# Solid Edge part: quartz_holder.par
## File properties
Title: Quartz Window Clamp
Author: Lee Sichello
Template: Iso Part.par
Last saved by: Lee
Revision: 70
Application: Solid Edge
Material: Aluminum
Face Style: Steel
Fill Style: ANSI32(Steel)
Virtual Style: Machined steel
Coef. of Thermal Exp: 1.3e-05
Thermal Conductivity: 32.0
Specific Heat: 481.0
Modulus of Elasticity: 199947953000.0
Poisson's Ratio: 0.29
Yield Stress: 262000766.0
Ultimate Stress: 358527364.0
Elongation: 0.0
Manager: Gath Huber
Company: U of R Physics
Density: 7833.000 kg/m^3
Accuracy: 0.990
Document Number: 4
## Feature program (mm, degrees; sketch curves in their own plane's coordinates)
sketch for "unnamed Protrusion 1" plane through (0, 0, 0) normal (0, 0, 1) x-axis (1, 0, 0)
  circle centre (0, 0) radius 109.5375
extrude "unnamed Protrusion 1" add finite 25.4 along +normal
sketch for "ExtrudedCutout_1" plane through (0, 0, 25.4) normal (0, 0, 1) x-axis (1, 0, 0)
  circle centre (0, 0) radius 92
extrude "ExtrudedCutout_1" cut finite 10 along -normal
sketch for "unnamed Cutout 1" plane through (0, 0, 15.4) normal (0, 0, 1) x-axis (1, 0, 0)
  circle centre (0, 0) radius 82
extrude "unnamed Cutout 1" cut to key point along -normal
chamfer "Chamfer_2" setback 10.4
fillet "Round_1" radius 1.5875
sketch for "Hole_18" plane through (0, 0, 0) normal (0, 0, -1) x-axis (0, 1, 0)
hole "Hole_18" diameter 8 through  CounterBoreDepth = 7.87 mm
sketch for "unnamed Hole 1" plane through (0, 0, 0) normal (0, 0, -1) x-axis (0, 1, 0)
hole "unnamed Hole 1" through
sketch for "unnamed Hole 2" plane through (0, 0, 0) normal (0, 0, -1) x-axis (0, 1, 0)
  hole centre (70.9016, 70.9016) bore radius 3.3235
hole "unnamed Hole 2" through
sketch for "unnamed Hole 3" plane through (0, 0, 0) normal (0, 0, -1) x-axis (0, 1, 0)
  hole centre (0, -100.27) bore radius 3.3235
hole "unnamed Hole 3" through
sketch for "unnamed Hole 4" plane through (0, 0, 0) normal (0, 0, -1) x-axis (0, 1, 0)
  hole centre (-70.9016, 70.9016) bore radius 3.3235
hole "unnamed Hole 4" through
sketch for "unnamed Hole 5" plane through (0, 0, 0) normal (0, 0, -1) x-axis (0, 1, 0)
  hole centre (-100.27, 0) bore radius 3.3235
hole "unnamed Hole 5" through
sketch for "unnamed Hole 6" plane through (0, 0, 0) normal (0, 0, -1) x-axis (0, 1, 0)
  hole centre (-70.9016, -70.9016) bore radius 3.3235
hole "unnamed Hole 6" through
sketch for "unnamed Hole 7" plane through (0, 0, 0) normal (0, 0, -1) x-axis (0, 1, 0)
  hole centre (70.9016, -70.9016) bore radius 3.3235
hole "unnamed Hole 7" through
pattern "unnamed Pattern 1" of "Hole_18", "unnamed Hole 1", "unnamed Hole 2", "unnamed Hole 3", "unnamed Hole 4", "unnamed Hole 5", "unnamed Hole 6", "unnamed Hole 7"
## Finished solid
Body 1: solid body, 32 faces, 40 edges, 0 vertices.
  Faces by surface: cylinder 19, plane 11, cone 1, torus 1
  Edges by curve: circle 40
Bounding box of the edges (mm; curved faces can reach further): 219.075 x 219.075 x 25.400, from (-109.5375, -109.5375, 0) to (109.5375, 109.5375, 25.4).
Cylindrical faces by radius (mm): R3.3235 x8, R6.5 x8, R82 x1, R92 x1, R109.5375 x1
Conical faces (half-angle, radius in mm at the cone's reference point): 45 deg R82 x1
Toroidal faces (ring radius, tube radius in mm): R83.5875 r1.5875 x1
Planar faces by outward normal: +z 2, -z 9
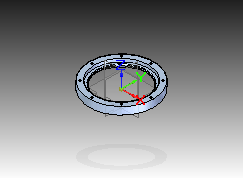
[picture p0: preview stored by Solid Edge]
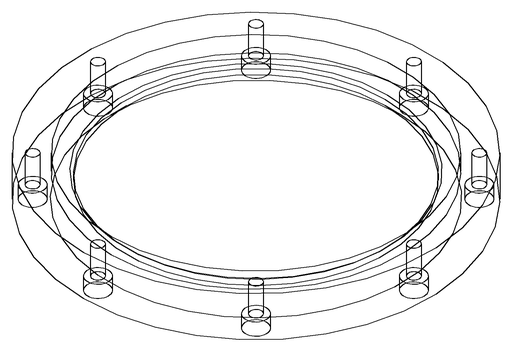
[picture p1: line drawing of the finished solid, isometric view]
